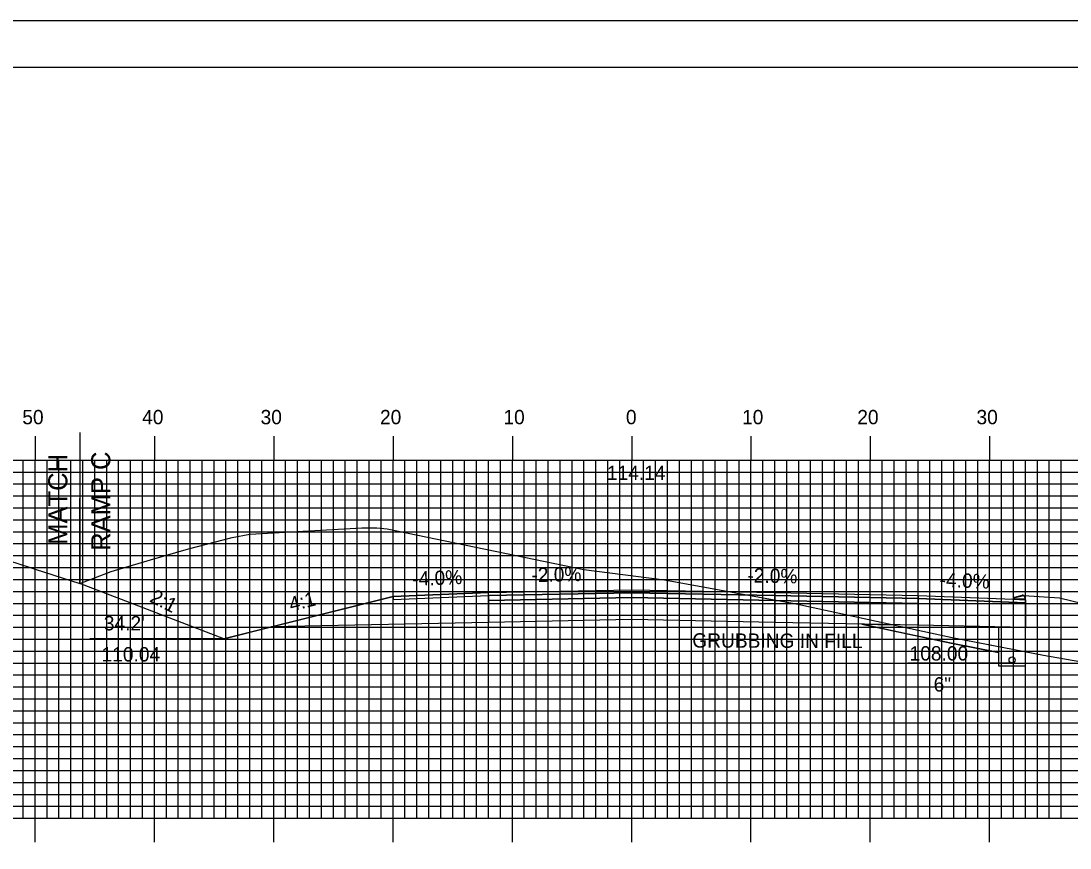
# Model space of a CAD drawing. Extents: x 1754708 to 1755051, y 442591 to 442811.
# Drawn here: x 1754822.3 to 1754910.3, y 442741.3 to 442810.5 of the extents above; entities that cross this region are included whole.
import ezdxf

# ---------------------------------------------------------------- set-up
doc = ezdxf.new("R2010")
doc.units = 0
for name, color, linetype in [('ANNOTATION', 7, 'Continuous'), ('BORDER', 7, 'Continuous'), ('D_Curb_Type_3M3_Rt', 7, 'Continuous'), ('D_Roadway_Centerline', 7, 'Continuous'), ('D_Roadway_Centerline_Text', 7, 'Continuous'), ('D_Roadway_Edge_Shoulder', 7, 'Continuous'), ('D_Roadway_Edge_TW', 7, 'Continuous'), ('D_Roadway_Pavement', 7, 'Continuous'), ('D_Roadway_SlopeLines', 7, 'Continuous'), ('D_Roadway_SubGrade', 7, 'Continuous'), ('GRUBBING IN FILL', 7, 'Continuous'), ('H_V ANNOTATION', 7, 'Continuous'), ('MAJOR', 7, 'Continuous'), ('MINOR', 7, 'Continuous'), ('PDRAIN', 7, 'Continuous'), ('PLOT BOUNDARY', 7, 'Continuous'), ('S_Roadway_Centerline', 7, 'Continuous')]:
    doc.layers.add(name, color=color, linetype=linetype)

msp = doc.modelspace()

# ---------------------------------------------------------------- linework, layer by layer
at = {"layer": 'BORDER'}
msp.add_lwpolyline([(1754723.917, 442596.665), (1755043.917, 442596.665), (1755043.917, 442806.665), (1754723.917, 442806.665)], close=True, dxfattribs=at)
at = {"layer": 'D_Curb_Type_3M3_Rt'}
for p, q in [((1754906.497, 442762.113), (1754905.517, 442762.113)), ((1754905.64, 442762.274), (1754906.244, 442762.441)), ((1754906.451, 442762.317), (1754906.497, 442762.113))]:
    msp.add_line(p, q, dxfattribs=at)
for centre, start, end in [((1754905.684, 442762.113), 105.42216, 180), ((1754906.288, 442762.28), 12.68038, 105.42216)]:
    msp.add_arc(centre, 0.167, start, end, dxfattribs=at)
at = {"layer": 'D_Roadway_Centerline'}
msp.add_lwpolyline([(1754839.343, 442758.81), (1754843.343, 442759.81), (1754853.517, 442762.353), (1754861.517, 442762.673), (1754873.517, 442762.913), (1754885.517, 442762.673), (1754897.517, 442762.433), (1754905.517, 442762.113), (1754905.528, 442762.166), (1754905.556, 442762.213), (1754905.596, 442762.248), (1754905.646, 442762.269), (1754906.256, 442762.411), (1754906.323, 442762.413), (1754906.386, 442762.388), (1754906.433, 442762.341), (1754906.458, 442762.279), (1754906.496, 442762.074), (1754906.517, 442762.073)], dxfattribs=at)
at = {"layer": 'D_Roadway_Edge_Shoulder'}
for points in [[(1754861.517, 442762.673), (1754853.517, 442762.353), (1754853.517, 442762.103), (1754861.517, 442762.423)], [(1754897.517, 442762.433), (1754905.517, 442762.113), (1754906.517, 442762.073), (1754906.517, 442761.823), (1754897.517, 442762.183)]]:
    msp.add_lwpolyline(points, close=True, dxfattribs=at)
at = {"layer": 'D_Roadway_Edge_TW'}
for points in [[(1754861.517, 442762.423), (1754861.517, 442762.673), (1754873.517, 442762.913), (1754885.517, 442762.673), (1754885.517, 442762.423), (1754873.517, 442762.663)], [(1754885.517, 442762.673), (1754897.517, 442762.433), (1754897.517, 442762.183), (1754885.517, 442762.423)]]:
    msp.add_lwpolyline(points, close=True, dxfattribs=at)
at = {"layer": 'D_Roadway_Pavement'}
for points in [[(1754861.517, 442762.007), (1754861.517, 442762.423), (1754873.517, 442762.663), (1754885.517, 442762.423), (1754885.517, 442762.007), (1754873.517, 442762.247)], [(1754885.517, 442762.423), (1754897.517, 442762.183), (1754897.517, 442761.767), (1754885.517, 442762.007)]]:
    msp.add_lwpolyline(points, close=True, dxfattribs=at)
msp.add_lwpolyline([(1754897.517, 442762.183), (1754897.517, 442761.767)], dxfattribs=at)
msp.add_lwpolyline([(1754897.517, 442762.183), (1754897.517, 442761.767)], dxfattribs=at)
msp.add_lwpolyline([(1754897.517, 442762.183), (1754897.517, 442761.767)], dxfattribs=at)
msp.add_lwpolyline([(1754897.517, 442762.183), (1754897.517, 442761.767)], dxfattribs=at)
at = {"layer": 'D_Roadway_SlopeLines'}
for p, q in [((1754827.269, 442763.424), (1754827.269, 442770.549)), ((1754839.343, 442758.81), (1754827.269, 442763.424)), ((1754906.374, 442762.423), (1754909.374, 442762.243)), ((1754909.374, 442762.243), (1754913.374, 442761.243))]:
    msp.add_line(p, q, dxfattribs=at)
msp.add_lwpolyline([(1754853.517, 442762.353), (1754839.343, 442758.81)], dxfattribs=at)
at = {"layer": 'D_Roadway_SubGrade'}
msp.add_line((1754827.269, 442776.088), (1754827.269, 442763.424), dxfattribs=at)
for points in [[(1754853.517, 442762.103), (1754861.517, 442762.423), (1754861.517, 442762.007), (1754861.517, 442760.173), (1754843.343, 442759.81), (1754853.517, 442762.353)], [(1754861.517, 442760.173), (1754861.517, 442762.007), (1754873.517, 442762.247), (1754885.517, 442762.007), (1754885.517, 442760.173), (1754873.517, 442760.413)], [(1754885.517, 442762.007), (1754897.517, 442761.767), (1754897.517, 442759.933), (1754885.517, 442760.173)], [(1754897.517, 442761.767), (1754897.517, 442762.183), (1754906.517, 442761.823), (1754906.517, 442759.753), (1754897.517, 442759.933)]]:
    msp.add_lwpolyline(points, close=True, dxfattribs=at)
at = {"layer": 'GRUBBING IN FILL'}
msp.add_lwpolyline([(1754892.816, 442760.027), (1754900.28, 442758.43), (1754904.269, 442757.654)], dxfattribs=at)
msp.add_lwpolyline([(1754892.816, 442760.027), (1754900.28, 442758.43), (1754904.269, 442757.654)], dxfattribs=at)
msp.add_lwpolyline([(1754892.816, 442760.027), (1754895.453, 442759.975), (1754900.38, 442758.92), (1754904.269, 442758.163), (1754904.269, 442757.654), (1754902.275, 442758.042), (1754900.28, 442758.43), (1754896.548, 442759.229)], close=True, dxfattribs=at)
msp.add_lwpolyline([(1754892.816, 442760.027), (1754895.453, 442759.975), (1754900.38, 442758.92), (1754904.269, 442758.163), (1754904.269, 442757.654), (1754902.275, 442758.042), (1754900.28, 442758.43), (1754896.548, 442759.229)], close=True, dxfattribs=at)
at = {"layer": 'MAJOR'}
for p, q in [((1754823.517, 442775.774), (1754823.517, 442773.77)), ((1754833.517, 442775.774), (1754833.517, 442773.77)), ((1754843.517, 442775.774), (1754843.517, 442773.77)), ((1754853.517, 442775.774), (1754853.517, 442773.77)), ((1754863.517, 442775.774), (1754863.517, 442773.77)), ((1754873.517, 442775.774), (1754873.517, 442773.77)), ((1754883.517, 442775.774), (1754883.517, 442773.77)), ((1754893.517, 442775.774), (1754893.517, 442773.77)), ((1754903.517, 442775.774), (1754903.517, 442773.77)), ((1754733.517, 442773.77), (1755013.517, 442773.77)), ((1754733.517, 442773.77), (1755013.517, 442773.77)), ((1754823.517, 442743.77), (1754823.517, 442773.77)), ((1754833.517, 442743.77), (1754833.517, 442773.77)), ((1754843.517, 442743.77), (1754843.517, 442773.77)), ((1754853.517, 442743.77), (1754853.517, 442773.77)), ((1754863.517, 442743.77), (1754863.517, 442773.77)), ((1754873.517, 442743.77), (1754873.517, 442773.77)), ((1754883.517, 442743.77), (1754883.517, 442773.77)), ((1754893.517, 442743.77), (1754893.517, 442773.77)), ((1754903.517, 442743.77), (1754903.517, 442773.77)), ((1754733.517, 442768.77), (1755013.517, 442768.77)), ((1754733.517, 442763.77), (1755013.517, 442763.77)), ((1754733.517, 442758.77), (1755013.517, 442758.77)), ((1754733.517, 442753.77), (1755013.517, 442753.77)), ((1754733.517, 442748.77), (1755013.517, 442748.77)), ((1754733.517, 442743.77), (1755013.517, 442743.77)), ((1754733.517, 442743.77), (1755013.517, 442743.77)), ((1754823.517, 442741.766), (1754823.517, 442743.77)), ((1754833.517, 442741.766), (1754833.517, 442743.77)), ((1754843.517, 442741.766), (1754843.517, 442743.77)), ((1754853.517, 442741.766), (1754853.517, 442743.77)), ((1754863.517, 442741.766), (1754863.517, 442743.77)), ((1754873.517, 442741.766), (1754873.517, 442743.77)), ((1754883.517, 442741.766), (1754883.517, 442743.77)), ((1754893.517, 442741.766), (1754893.517, 442743.77)), ((1754903.517, 442741.766), (1754903.517, 442743.77))]:
    msp.add_line(p, q, dxfattribs=at)
at = {"layer": 'MINOR'}
for p, q in [((1754822.517, 442743.77), (1754822.517, 442773.77)), ((1754824.517, 442743.77), (1754824.517, 442773.77)), ((1754825.517, 442743.77), (1754825.517, 442773.77)), ((1754826.517, 442743.77), (1754826.517, 442773.77)), ((1754827.517, 442743.77), (1754827.517, 442773.77)), ((1754828.517, 442743.77), (1754828.517, 442773.77)), ((1754829.517, 442743.77), (1754829.517, 442773.77)), ((1754830.517, 442743.77), (1754830.517, 442773.77)), ((1754831.517, 442743.77), (1754831.517, 442773.77)), ((1754832.517, 442743.77), (1754832.517, 442773.77)), ((1754834.517, 442743.77), (1754834.517, 442773.77)), ((1754835.517, 442743.77), (1754835.517, 442773.77)), ((1754836.517, 442743.77), (1754836.517, 442773.77)), ((1754837.517, 442743.77), (1754837.517, 442773.77)), ((1754838.517, 442743.77), (1754838.517, 442773.77)), ((1754839.517, 442743.77), (1754839.517, 442773.77)), ((1754840.517, 442743.77), (1754840.517, 442773.77)), ((1754841.517, 442743.77), (1754841.517, 442773.77)), ((1754842.517, 442743.77), (1754842.517, 442773.77)), ((1754844.517, 442743.77), (1754844.517, 442773.77)), ((1754845.517, 442743.77), (1754845.517, 442773.77)), ((1754846.517, 442743.77), (1754846.517, 442773.77)), ((1754847.517, 442743.77), (1754847.517, 442773.77)), ((1754848.517, 442743.77), (1754848.517, 442773.77)), ((1754849.517, 442743.77), (1754849.517, 442773.77)), ((1754850.517, 442743.77), (1754850.517, 442773.77)), ((1754851.517, 442743.77), (1754851.517, 442773.77)), ((1754852.517, 442743.77), (1754852.517, 442773.77)), ((1754854.517, 442743.77), (1754854.517, 442773.77)), ((1754855.517, 442743.77), (1754855.517, 442773.77)), ((1754856.517, 442743.77), (1754856.517, 442773.77)), ((1754857.517, 442743.77), (1754857.517, 442773.77)), ((1754858.517, 442743.77), (1754858.517, 442773.77)), ((1754859.517, 442743.77), (1754859.517, 442773.77)), ((1754860.517, 442743.77), (1754860.517, 442773.77)), ((1754861.517, 442743.77), (1754861.517, 442773.77)), ((1754862.517, 442743.77), (1754862.517, 442773.77)), ((1754864.517, 442743.77), (1754864.517, 442773.77)), ((1754865.517, 442743.77), (1754865.517, 442773.77)), ((1754866.517, 442743.77), (1754866.517, 442773.77)), ((1754867.517, 442743.77), (1754867.517, 442773.77)), ((1754868.517, 442743.77), (1754868.517, 442773.77)), ((1754869.517, 442743.77), (1754869.517, 442773.77)), ((1754870.517, 442743.77), (1754870.517, 442773.77)), ((1754871.517, 442743.77), (1754871.517, 442773.77)), ((1754872.517, 442743.77), (1754872.517, 442773.77)), ((1754874.517, 442743.77), (1754874.517, 442773.77)), ((1754875.517, 442743.77), (1754875.517, 442773.77)), ((1754876.517, 442743.77), (1754876.517, 442773.77)), ((1754877.517, 442743.77), (1754877.517, 442773.77)), ((1754878.517, 442743.77), (1754878.517, 442773.77)), ((1754879.517, 442743.77), (1754879.517, 442773.77)), ((1754880.517, 442743.77), (1754880.517, 442773.77)), ((1754881.517, 442743.77), (1754881.517, 442773.77)), ((1754882.517, 442743.77), (1754882.517, 442773.77)), ((1754884.517, 442743.77), (1754884.517, 442773.77)), ((1754885.517, 442743.77), (1754885.517, 442773.77)), ((1754886.517, 442743.77), (1754886.517, 442773.77)), ((1754887.517, 442743.77), (1754887.517, 442773.77)), ((1754888.517, 442743.77), (1754888.517, 442773.77)), ((1754889.517, 442743.77), (1754889.517, 442773.77)), ((1754890.517, 442743.77), (1754890.517, 442773.77)), ((1754891.517, 442743.77), (1754891.517, 442773.77)), ((1754892.517, 442743.77), (1754892.517, 442773.77)), ((1754894.517, 442743.77), (1754894.517, 442773.77)), ((1754895.517, 442743.77), (1754895.517, 442773.77)), ((1754896.517, 442743.77), (1754896.517, 442773.77)), ((1754897.517, 442743.77), (1754897.517, 442773.77)), ((1754898.517, 442743.77), (1754898.517, 442773.77)), ((1754899.517, 442743.77), (1754899.517, 442773.77)), ((1754900.517, 442743.77), (1754900.517, 442773.77)), ((1754901.517, 442743.77), (1754901.517, 442773.77)), ((1754902.517, 442743.77), (1754902.517, 442773.77)), ((1754904.517, 442743.77), (1754904.517, 442773.77)), ((1754905.517, 442743.77), (1754905.517, 442773.77)), ((1754906.517, 442743.77), (1754906.517, 442773.77)), ((1754907.517, 442743.77), (1754907.517, 442773.77)), ((1754908.517, 442743.77), (1754908.517, 442773.77)), ((1754909.517, 442743.77), (1754909.517, 442773.77)), ((1754733.517, 442772.77), (1755013.517, 442772.77)), ((1754733.517, 442771.77), (1755013.517, 442771.77)), ((1754733.517, 442770.77), (1755013.517, 442770.77)), ((1754733.517, 442769.77), (1755013.517, 442769.77)), ((1754733.517, 442767.77), (1755013.517, 442767.77)), ((1754733.517, 442766.77), (1755013.517, 442766.77)), ((1754733.517, 442765.77), (1755013.517, 442765.77)), ((1754733.517, 442764.77), (1755013.517, 442764.77)), ((1754733.517, 442762.77), (1755013.517, 442762.77)), ((1754733.517, 442761.77), (1755013.517, 442761.77)), ((1754733.517, 442760.77), (1755013.517, 442760.77)), ((1754733.517, 442759.77), (1755013.517, 442759.77)), ((1754733.517, 442757.77), (1755013.517, 442757.77)), ((1754733.517, 442756.77), (1755013.517, 442756.77)), ((1754733.517, 442755.77), (1755013.517, 442755.77)), ((1754733.517, 442754.77), (1755013.517, 442754.77)), ((1754733.517, 442752.77), (1755013.517, 442752.77)), ((1754733.517, 442751.77), (1755013.517, 442751.77)), ((1754733.517, 442750.77), (1755013.517, 442750.77)), ((1754733.517, 442749.77), (1755013.517, 442749.77)), ((1754733.517, 442747.77), (1755013.517, 442747.77)), ((1754733.517, 442746.77), (1755013.517, 442746.77)), ((1754733.517, 442745.77), (1755013.517, 442745.77)), ((1754733.517, 442744.77), (1755013.517, 442744.77))]:
    msp.add_line(p, q, dxfattribs=at)
at = {"layer": 'PDRAIN'}
for p, q in [((1754828.117, 442758.811), (1754839.34, 442758.811)), ((1754896.671, 442756.776), (1754905.394, 442756.776))]:
    msp.add_line(p, q, dxfattribs=at)
msp.add_lwpolyline([(1754904.269, 442759.798), (1754904.269, 442756.526), (1754906.519, 442756.526), (1754906.519, 442759.753)], dxfattribs=at)
msp.add_circle((1754905.394, 442757.026), 0.25, dxfattribs=at)
at = {"layer": 'PLOT BOUNDARY'}
msp.add_lwpolyline([(1754707.731, 442590.547), (1755047.731, 442590.547), (1755047.731, 442810.547), (1754707.731, 442810.547)], close=True, dxfattribs=at)
at = {"layer": 'S_Roadway_Centerline'}
for points in [[(1754827.267, 442763.43), (1754829.88, 442764.431), (1754833.203, 442765.405), (1754836.387, 442766.328), (1754840.035, 442767.272), (1754841.507, 442767.565), (1754850.897, 442768.089), (1754852.158, 442768.101), (1754853.03, 442768.015), (1754869.519, 442764.598), (1754876.271, 442763.75), (1754887.307, 442761.718), (1754900.38, 442758.92), (1754908.03, 442757.431), (1754918.443, 442755.606), (1754927.18, 442753.579), (1754931.54, 442753.433)], [(1754821.286, 442765.354), (1754823.098, 442764.769), (1754823.098, 442764.769), (1754823.098, 442764.769), (1754823.522, 442764.633), (1754827.269, 442763.424), (1754827.271, 442763.425), (1754827.311, 442763.441)]]:
    msp.add_lwpolyline(points, dxfattribs=at)

# ---------------------------------------------------------------- texts
at = {"layer": 'ANNOTATION'}
for s, height, rotation, p in [('RAMP C', 1.6, 90, (1754829.822, 442766.166)), ('MATCH', 1.6, 90, (1754826.222, 442766.673)), ('-4.0%', 1.2, 2.29061, (1754855.149, 442763.22)), ('-2.0%', 1.2, 1.14576, (1754865.124, 442763.546)), ('-2.0%', 1.2, 358.85424, (1754883.204, 442763.52)), ('-4.0%', 1.2, 357.70939, (1754899.309, 442763.163)), ('2:1', 1.2, 333.29318, (1754833.047, 442761.938)), ('4:1', 1.2, 14.03624, (1754844.966, 442761.077))]:
    msp.add_text(s, height=height, rotation=rotation, dxfattribs=at).set_placement(p)
for s, p in [("34.2'", (1754829.278, 442759.503)), ('110.04', (1754829.091, 442756.903)), ('108.00', (1754896.81, 442756.981)), ('6"', (1754898.822, 442754.381))]:
    msp.add_text(s, height=1.2, dxfattribs=at).set_placement(p)
at = {"layer": 'D_Roadway_Centerline'}
for s, p in [('C', (1754873.512, 442762.913)), ('L', (1754873.517, 442762.906))]:
    msp.add_text(s, height=0.0146, dxfattribs=at).set_placement(p)
at = {"layer": 'D_Roadway_Centerline_Text'}
msp.add_text('114.14', height=1.2, dxfattribs=at).set_placement((1754871.442, 442772.101))
at = {"layer": 'GRUBBING IN FILL'}
msp.add_text('GRUBBING IN FILL', height=1.2, rotation=359.81416, dxfattribs=at).set_placement((1754878.596, 442758.065))
at = {"layer": 'H_V ANNOTATION'}
for s, p in [('50', (1754822.447, 442776.77)), ('40', (1754832.49, 442776.77)), ('30', (1754842.415, 442776.77)), ('20', (1754852.425, 442776.77)), ('10', (1754862.768, 442776.77)), ('0', (1754873.036, 442776.77)), ('10', (1754882.768, 442776.77)), ('20', (1754892.425, 442776.77)), ('30', (1754902.415, 442776.77))]:
    msp.add_text(s, height=1.2, dxfattribs=at).set_placement(p)

doc.saveas('drawing.dxf')
